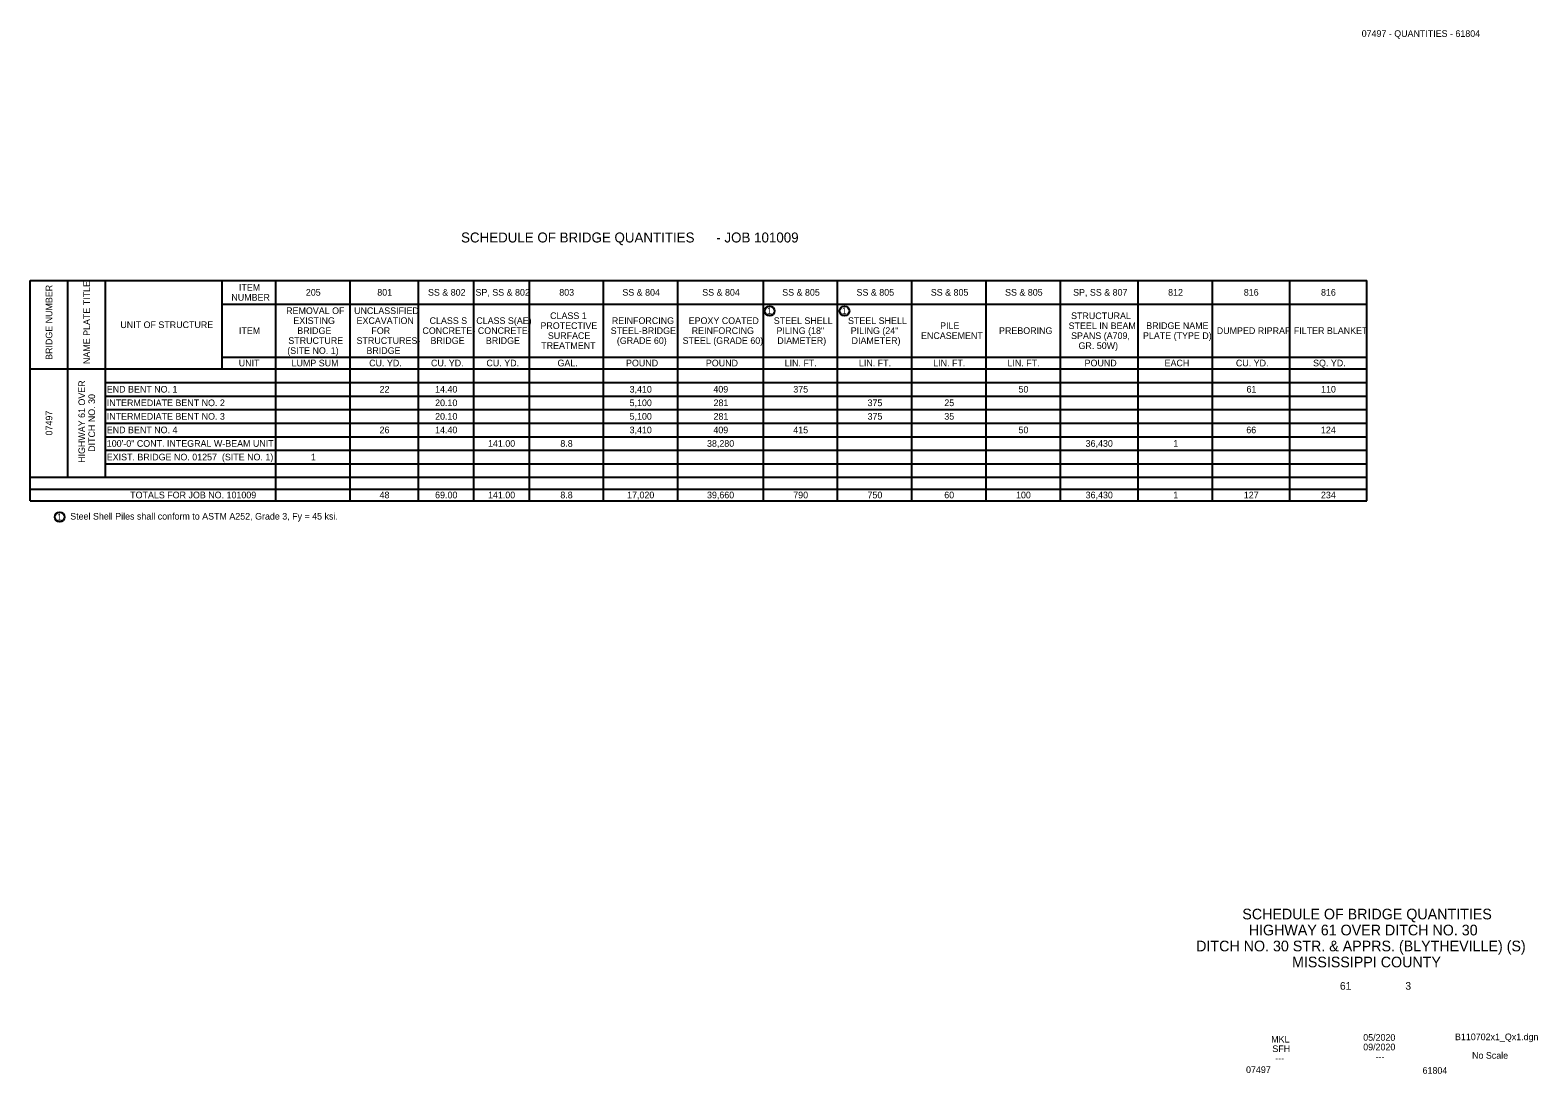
# Model space of a CAD drawing. Extents: x 192.8 to 249.4, y 129.2 to 148.9.
# Drawn here: x 192.85 to 221.19, y 129.23 to 148.86 of the extents above; entities that cross this region are included whole.
import ezdxf

# ---------------------------------------------------------------- set-up
doc = ezdxf.new("R2010")
doc.units = 0
for name, color, linetype in [('B_Copy In', 7, 'Continuous'), ('B_Dimensions', 7, 'Continuous'), ('B_Text', 7, 'Continuous'), ('B_Title Text', 7, 'Continuous')]:
    doc.layers.add(name, color=color, linetype=linetype)

msp = doc.modelspace()

# ---------------------------------------------------------------- linework, layer by layer
at = {"layer": 'B_Dimensions'}
msp.add_line((192.847, 144.151), (192.847, 144.151), dxfattribs=at)
at = {"layer": 'B_Text'}
for p, q in [((192.847, 144.151), (217.976, 144.151)), ((192.847, 140.007), (192.847, 144.151)), ((193.556, 140.451), (193.556, 144.151)), ((194.265, 140.451), (194.265, 144.151)), ((196.459, 142.489), (196.459, 144.151)), ((197.467, 140.007), (197.467, 144.151)), ((198.863, 140.007), (198.863, 144.151)), ((200.148, 140.007), (200.148, 144.151)), ((201.19, 140.007), (201.19, 144.151)), ((202.231, 140.007), (202.231, 144.151)), ((203.627, 140.007), (203.627, 144.151)), ((205.023, 140.007), (205.023, 144.151)), ((206.63, 140.007), (206.63, 144.151)), ((208.026, 140.007), (208.026, 144.151)), ((209.422, 140.007), (209.422, 144.151)), ((210.818, 140.007), (210.818, 144.151)), ((212.214, 140.007), (212.214, 144.151)), ((213.677, 140.007), (213.677, 144.151)), ((215.073, 140.007), (215.073, 144.151)), ((216.524, 140.007), (216.524, 144.151)), ((217.976, 140.007), (217.976, 144.151)), ((196.459, 143.708), (217.976, 143.708)), ((196.459, 142.711), (217.976, 142.711)), ((192.847, 142.489), (217.976, 142.489)), ((194.265, 142.234), (217.976, 142.234)), ((194.265, 141.98), (217.976, 141.98)), ((194.265, 141.725), (217.976, 141.725)), ((194.265, 141.47), (217.976, 141.47)), ((194.265, 141.215), (217.976, 141.215)), ((194.265, 140.96), (217.976, 140.96)), ((194.265, 140.705), (217.976, 140.705)), ((192.847, 140.451), (217.976, 140.451)), ((192.847, 140.229), (217.976, 140.229)), ((192.847, 140.007), (217.976, 140.007))]:
    msp.add_line(p, q, dxfattribs=at)
for centre in [(206.749, 143.581), (208.155, 143.581), (193.403, 139.703)]:
    msp.add_circle(centre, 0.0914, dxfattribs=at)

# ---------------------------------------------------------------- texts
at = {"layer": 'B_Copy In'}
for s, height, p in [('07497 - QUANTITIES - 61804', 0.1248, (217.877, 148.735)), ('SCHEDULE OF BRIDGE QUANTITIES', 0.2004, (215.633, 132.137)), ('HIGHWAY 61 OVER DITCH NO. 30', 0.2004, (215.753, 131.836)), ('DITCH NO. 30 STR. & APPRS. (BLYTHEVILLE) (S)', 0.2004, (214.765, 131.536)), ('MISSISSIPPI COUNTY', 0.2004, (216.567, 131.235)), ('MKL', 0.1248, (216.176, 129.821)), ('05/2020', 0.1248, (217.906, 129.854)), ('09/2020', 0.1248, (217.906, 129.674)), ('B110702x1_Qx1.dgn', 0.1248, (219.631, 129.865)), ('SFH', 0.1248, (216.198, 129.641)), ('---', 0.1248, (218.139, 129.487)), ('No Scale', 0.1248, (219.952, 129.516)), ('07497', 0.125, (215.703, 129.247)), ('---', 0.1248, (216.252, 129.461)), ('61804', 0.125, (219.021, 129.233))]:
    msp.add_text(s, height=height, dxfattribs=at).set_placement(p)
at = {"layer": 'B_Text'}
for s, height, p in [('SCHEDULE OF BRIDGE QUANTITIES', 0.1875, (200.947, 144.868)), (' - JOB 101009', 0.1875, (205.675, 144.868)), ('ITEM', 0.125, (196.772, 143.961)), ('205', 0.125, (198.029, 143.867)), ('801', 0.125, (199.372, 143.867)), ('SS & 802', 0.125, (200.325, 143.867)), ('SP, SS & 802', 0.125, (201.218, 143.867)), ('803', 0.125, (202.793, 143.867)), ('SS & 804', 0.125, (203.979, 143.867)), ('SS & 804', 0.125, (205.481, 143.867)), ('SS & 805', 0.125, (206.984, 143.867)), ('SS & 805', 0.125, (208.381, 143.867)), ('SS & 805', 0.125, (209.777, 143.867)), ('SS & 805', 0.125, (211.173, 143.867)), ('SP, SS & 807', 0.125, (212.452, 143.867)), ('812', 0.125, (214.238, 143.867)), ('816', 0.125, (215.661, 143.867)), ('816', 0.125, (217.112, 143.867)), ('NUMBER', 0.125, (196.629, 143.773)), ('REMOVAL OF', 0.125, (197.659, 143.522)), ('EXISTING', 0.125, (197.794, 143.335)), ('UNCLASSIFIED', 0.125, (198.936, 143.522)), (' EXCAVATION', 0.125, (198.936, 143.335)), ('CLASS S', 0.125, (200.355, 143.335)), ('CLASS S(AE)', 0.125, (201.233, 143.335)), ('CLASS 1', 0.125, (202.621, 143.428)), ('REINFORCING', 0.125, (203.781, 143.335)), ('EPOXY COATED', 0.125, (205.226, 143.335)), ('1', 0.125, (206.698, 143.519)), ('STEEL SHELL', 0.125, (206.825, 143.335)), ('1', 0.125, (208.104, 143.519)), ('STEEL SHELL', 0.125, (208.221, 143.335)), (' STRUCTURAL', 0.125, (212.368, 143.427)), ('UNIT OF STRUCTURE', 0.125, (194.542, 143.258)), ('ITEM', 0.125, (196.772, 143.147)), ('BRIDGE', 0.125, (197.868, 143.147)), ('       FOR', 0.125, (198.936, 143.147)), ('CONCRETE-', 0.125, (200.22, 143.147)), ('CONCRETE-', 0.125, (201.262, 143.147)), ('PROTECTIVE', 0.125, (202.439, 143.241)), ('SURFACE', 0.125, (202.578, 143.053)), ('STEEL-BRIDGE', 0.125, (203.76, 143.147)), ('REINFORCING', 0.125, (205.282, 143.147)), ('PILING (18"', 0.125, (206.876, 143.147)), ('PILING (24"', 0.125, (208.272, 143.147)), ('ENCASEMENT', 0.125, (209.593, 143.053)), ('PILE', 0.125, (209.952, 143.241)), ('PREBORING', 0.125, (211.06, 143.147)), ('STEEL IN BEAM', 0.125, (212.368, 143.239)), (' SPANS (A709,', 0.125, (212.368, 143.052)), ('PLATE (TYPE D)', 0.125, (213.766, 143.053)), ('BRIDGE NAME', 0.125, (213.827, 143.241)), ('DUMPED RIPRAP', 0.125, (215.153, 143.147)), ('FILTER BLANKET', 0.125, (216.601, 143.147)), ('(SITE NO. 1)', 0.125, (197.68, 142.772)), ('STRUCTURE', 0.125, (197.7, 142.96)), (' STRUCTURES-', 0.125, (198.936, 142.96)), ('     BRIDGE', 0.125, (198.936, 142.772)), ('BRIDGE', 0.125, (200.372, 142.96)), ('BRIDGE', 0.125, (201.413, 142.96)), ('TREATMENT', 0.125, (202.454, 142.866)), ('(GRADE 60)', 0.125, (203.875, 142.96)), ('STEEL (GRADE 60)', 0.125, (205.112, 142.96)), ('DIAMETER)', 0.125, (206.891, 142.96)), ('DIAMETER)', 0.125, (208.288, 142.96)), ('    GR. 50W)', 0.125, (212.368, 142.864)), ('UNIT', 0.125, (196.767, 142.538)), ('LUMP SUM', 0.125, (197.761, 142.538)), ('CU. YD.', 0.125, (199.219, 142.538)), ('CU. YD.', 0.125, (200.382, 142.538)), ('CU. YD.', 0.125, (201.424, 142.538)), ('GAL.', 0.125, (202.76, 142.538)), ('POUND', 0.125, (204.048, 142.538)), ('POUND', 0.125, (205.549, 142.538)), ('LIN. FT.', 0.125, (207.03, 142.538)), ('LIN. FT.', 0.125, (208.426, 142.538)), ('LIN. FT.', 0.125, (209.822, 142.538)), ('LIN. FT.', 0.125, (211.218, 142.538)), ('POUND', 0.125, (212.668, 142.538)), ('EACH', 0.125, (214.172, 142.538)), ('CU. YD.', 0.125, (215.512, 142.538)), ('SQ. YD.', 0.125, (216.963, 142.538)), ('END BENT NO. 1', 0.125, (194.287, 142.045)), ('22', 0.125, (199.416, 142.045)), ('14.40', 0.125, (200.459, 142.045)), ('3,410', 0.125, (204.115, 142.045)), ('409', 0.125, (205.69, 142.045)), ('375', 0.125, (207.192, 142.045)), ('50', 0.125, (211.426, 142.045)), ('61', 0.125, (215.712, 142.045)), ('110', 0.125, (217.113, 142.045)), ('INTERMEDIATE BENT NO. 2', 0.125, (194.287, 141.79)), ('20.10', 0.125, (200.459, 141.79)), ('5,100', 0.125, (204.115, 141.79)), ('281', 0.125, (205.693, 141.79)), ('375', 0.125, (208.588, 141.79)), ('25', 0.125, (210.031, 141.79)), ('INTERMEDIATE BENT NO. 3', 0.125, (194.287, 141.535)), ('20.10', 0.125, (200.459, 141.535)), ('5,100', 0.125, (204.115, 141.535)), ('281', 0.125, (205.693, 141.535)), ('375', 0.125, (208.588, 141.535)), ('35', 0.125, (210.031, 141.535)), ('100\'-0" CONT. INTEGRAL W-BEAM UNIT', 0.125, (194.287, 141.025)), ('END BENT NO. 4', 0.125, (194.287, 141.28)), ('26', 0.125, (199.415, 141.28)), ('14.40', 0.125, (200.459, 141.28)), ('141.00', 0.125, (201.453, 141.025)), ('8.8', 0.125, (202.813, 141.025)), ('3,410', 0.125, (204.115, 141.28)), ('38,280', 0.125, (205.57, 141.025)), ('409', 0.125, (205.69, 141.28)), ('415', 0.125, (207.192, 141.28)), ('50', 0.125, (211.426, 141.28)), ('36,430', 0.125, (212.688, 141.025)), ('1', 0.125, (214.335, 141.025)), ('66', 0.125, (215.708, 141.28)), ('124', 0.125, (217.111, 141.28)), ('EXIST. BRIDGE NO. 01257  (SITE NO. 1)', 0.125, (194.287, 140.77)), ('1', 0.125, (198.125, 140.77)), ('TOTALS FOR JOB NO. 101009', 0.125, (194.727, 140.056)), ('48', 0.125, (199.415, 140.056)), ('69.00', 0.125, (200.459, 140.056)), ('141.00', 0.125, (201.453, 140.056)), ('8.8', 0.125, (202.813, 140.056)), ('17,020', 0.125, (204.068, 140.056)), ('39,660', 0.125, (205.57, 140.056)), ('790', 0.125, (207.191, 140.056)), ('750', 0.125, (208.587, 140.056)), ('60', 0.125, (210.03, 140.056)), ('100', 0.125, (211.379, 140.056)), ('36,430', 0.125, (212.688, 140.056)), ('1', 0.125, (214.335, 140.056)), ('127', 0.125, (215.661, 140.056)), ('234', 0.125, (217.111, 140.056)), ('1', 0.125, (193.352, 139.64)), ('Steel Shell Piles shall conform to ASTM A252, Grade 3, Fy = 45 ksi.', 0.125, (193.6, 139.656))]:
    msp.add_text(s, height=height, dxfattribs=at).set_placement(p)
for s, p in [('BRIDGE NUMBER', (193.264, 142.66)), ('NAME PLATE TITLE', (193.973, 142.582)), ('HIGHWAY 61 OVER', (193.879, 140.723)), ('DITCH NO. 30', (194.067, 140.931)), ('07497', (193.264, 141.239))]:
    msp.add_text(s, height=0.125, rotation=90, dxfattribs=at).set_placement(p)
at = {"layer": 'B_Title Text'}
msp.add_text('61                   3', height=0.144, dxfattribs=at).set_placement((217.468, 130.814))

doc.saveas('drawing.dxf')
